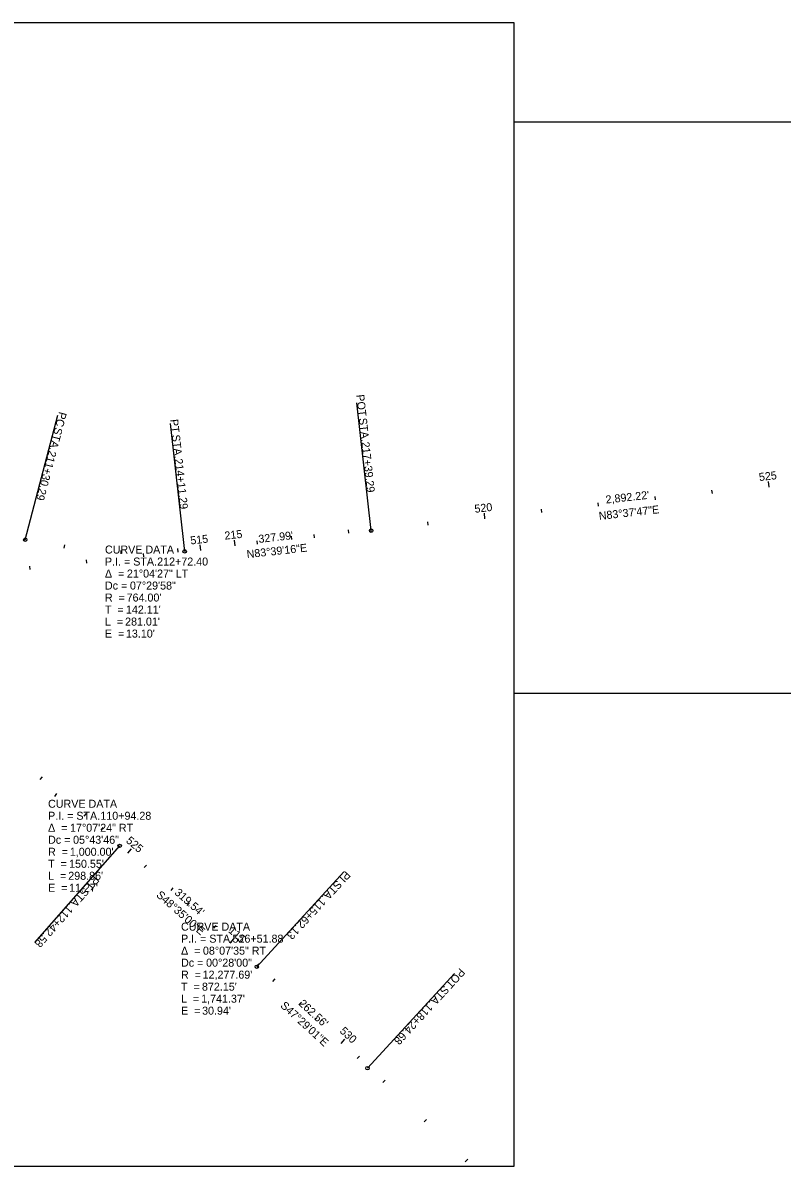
# Model space of a CAD drawing. Extents: x 1597353 to 1604853, y 283653 to 289007.
# Drawn here: x 1601495 to 1602822, y 285653 to 287653 of the extents above; entities that cross this region are included whole.
import ezdxf

# ---------------------------------------------------------------- set-up
doc = ezdxf.new("R2010")
doc.units = 0
for name, color, linetype in [('_CIVIL_CONSTRUCTION', 7, 'Continuous'), ('GE_X_Alignment_100_Cardinal_Points', 7, 'Continuous'), ('GE_X_Alignment_100_Distances', 7, 'Continuous'), ('GE_X_Alignment_100_Stations', 7, 'Continuous'), ('SH_Border', 7, 'Continuous'), ('SH_Cut_Line', 7, 'Continuous'), ('SH_Data', 7, 'Continuous'), ('SH_Masking', 7, 'Continuous'), ('SH_Named_Boundary', 7, 'Continuous'), ('SH_Text', 7, 'Continuous')]:
    doc.layers.add(name, color=color, linetype=linetype)

msp = doc.modelspace()

# ---------------------------------------------------------------- linework, layer by layer
at = {"layer": '_CIVIL_CONSTRUCTION'}
msp.add_line((1604853.4, 286480.4), (1602353.4, 286480.4), dxfattribs=at)
msp.add_lwpolyline([(1599853.4, 287653.4), (1599853.4, 285653.4), (1600103.4, 285653.4), (1600353.4, 285653.4), (1600603.4, 285653.4), (1600853.4, 285653.4), (1601103.4, 285653.4), (1601353.4, 285653.4), (1601603.4, 285653.4), (1601853.4, 285653.4), (1602103.4, 285653.4), (1602353.4, 285653.4), (1602353.4, 287653.4), (1602103.4, 287653.4), (1601853.4, 287653.4), (1601603.4, 287653.4), (1601353.4, 287653.4), (1601103.4, 287653.4), (1600853.4, 287653.4), (1600603.4, 287653.4), (1600353.4, 287653.4), (1600103.4, 287653.4)], close=True, dxfattribs=at)
msp.add_lwpolyline([(1602353.4, 286480.4), (1602353.4, 287480.4), (1604853.4, 287480.4), (1604853.4, 286480.4)], dxfattribs=at)
at = {"layer": 'GE_X_Alignment_100_Stations'}
for p, q in [((1602799.5, 286841.1), (1602798.4, 286851)), ((1602600.7, 286818.9), (1602600.1, 286824.9)), ((1602700.1, 286830), (1602699.4, 286836)), ((1602402, 286796.7), (1602401.3, 286802.7)), ((1602501.3, 286807.8), (1602500.7, 286813.8)), ((1602203.2, 286774.5), (1602202.5, 286780.5)), ((1602302.6, 286785.6), (1602301.5, 286795.6)), ((1602103.8, 286763.4), (1602103.2, 286769.4)), ((1601805.7, 286730.2), (1601804.6, 286740.1)), ((1601905.1, 286741.3), (1601904.4, 286747.2)), ((1602004.4, 286752.3), (1602003.8, 286758.3)), ((1601706.3, 286719.1), (1601705.6, 286725)), ((1601507.5, 286696.9), (1601506.9, 286702.8)), ((1601606.9, 286708), (1601606.2, 286713.9)), ((1601525.2, 286329.9), (1601529, 286334.5)), ((1601601.9, 286265.8), (1601605.8, 286270.4)), ((1601678.1, 286201), (1601684.6, 286208.6)), ((1601753.8, 286135.6), (1601757.7, 286140.2)), ((1601828.9, 286069.6), (1601832.9, 286074.1)), ((1601903.5, 286003), (1601907.5, 286007.5)), ((1601977.5, 285935.8), (1601981.6, 285940.3)), ((1602051, 285868), (1602057.9, 285875.4)), ((1602124, 285799.6), (1602128.1, 285804)), ((1602196.4, 285730.6), (1602200.5, 285735)), ((1602268.2, 285661.1), (1602272.4, 285665.4))]:
    msp.add_line(p, q, dxfattribs=at)
at = {"layer": 'SH_Border'}
for p, q in [((1602103.6, 286765.1), (1602078.8, 286988.7)), ((1601499, 286749.2), (1601556.2, 286966.9)), ((1601777.7, 286728.8), (1601752.8, 286952.4)), ((1601664, 286213.5), (1601515.2, 286044.8)), ((1601903.6, 286002.2), (1602055.7, 286168)), ((1602097.2, 285824.7), (1602249.2, 285990.6))]:
    msp.add_line(p, q, dxfattribs=at)
for centre in [(1602103.6, 286765.1), (1601499, 286749.2), (1601777.7, 286728.8), (1601664, 286213.5), (1601903.6, 286002.2), (1602097.2, 285824.7)]:
    msp.add_circle(centre, 3, dxfattribs=at)
at = {"layer": 'SH_Text'}
for p, q in [((1602064.6, 286760.7), (1602063.9, 286766.7)), ((1601567.1, 286734.6), (1601568.1, 286740.5)), ((1601865.8, 286738.6), (1601864.7, 286748.6)), ((1601965.2, 286749.7), (1601964.5, 286755.6)), ((1601666.5, 286724.6), (1601666.7, 286730.6)), ((1601766.4, 286727.7), (1601765.8, 286733.6)), ((1601550.7, 286299.9), (1601554, 286305)), ((1601631.5, 286241), (1601635.3, 286245.7)), ((1601707.1, 286175.6), (1601711, 286180.1)), ((1601782.1, 286109.4), (1601786, 286113.9)), ((1601857.1, 286043.3), (1601863.7, 286050.8)), ((1601931.6, 285976.6), (1601935.6, 285981)), ((1602005.3, 285909), (1602009.3, 285913.4)), ((1602079, 285841.4), (1602083, 285845.8))]:
    msp.add_line(p, q, dxfattribs=at)

# ---------------------------------------------------------------- texts
at = {"layer": 'GE_X_Alignment_100_Cardinal_Points'}
msp.add_text('N83°37\'47"E', height=14, rotation=6.3702, dxfattribs=at).set_placement((1602502.3, 286783.8))
at = {"layer": 'GE_X_Alignment_100_Distances'}
msp.add_text("2,892.22'", height=14, rotation=6.3702, dxfattribs=at).set_placement((1602514.3, 286812.4))
at = {"layer": 'GE_X_Alignment_100_Stations'}
for s, rotation, p in [('525', 6.3702, (1602782.2, 286851.8)), ('520', 6.3702, (1602285, 286796.2)), ('515', 6.3702, (1601788.3, 286740.8)), ('525', 319.4081, (1601674, 286220.9)), ('530', 317.0747, (1602047.6, 285888.3))]:
    msp.add_text(s, height=14, rotation=rotation, dxfattribs=at).set_placement(p)
at = {"layer": 'SH_Border'}
for s, rotation, p in [('POT', 276.3456, (1602077.4, 287002.5)), ('PC', 255.2715, (1601558.2, 286973.9)), (' STA. ', 276.3456, (1602081.4, 286966.7)), (' STA. ', 255.2715, (1601552.4, 286951.7)), ('PT', 276.3456, (1601752.2, 286959.3)), (' STA. ', 276.3456, (1601754.7, 286937.4)), ('211+30.29', 255.2715, (1601540.4, 286906)), ('217+39.29', 276.3456, (1602086.6, 286919.7)), ('214+11.29', 276.3456, (1601759.9, 286890.4)), ('PT', 228.5834, (1601619.2, 286162.4)), ('PI', 227.4836, (1602058.6, 286170.9)), (' STA. ', 228.5834, (1601604.6, 286145.8)), (' STA. ', 227.4836, (1602047.2, 286158.4)), ('115+62.13', 227.4836, (1602015.2, 286123.5)), ('112+42.58', 228.5834, (1601573.3, 286110.4)), ('POT', 227.4836, (1602258.8, 286000.7)), (' STA. ', 227.4836, (1602234.5, 285974.2)), ('118+24.68', 227.4836, (1602202.5, 285939.3))]:
    msp.add_text(s, height=14, rotation=rotation, dxfattribs=at).set_placement(p)
at = {"layer": 'SH_Cut_Line'}
for s, rotation, p in [('N83°39\'16"E', 6.3456, (1601886.8, 286716.8)), ('S48°35\'00"E', 318.5834, (1601726.9, 286126)), ('S47°29\'01"E', 317.4836, (1601943.9, 285932.7))]:
    msp.add_text(s, height=14, rotation=rotation, dxfattribs=at).set_placement(p)
at = {"layer": 'SH_Data'}
for s, p in [('CURVE DATA', (1601638.3, 286725)), ('P.I. = STA. ', (1601638.3, 286704)), ('212+72.40', (1601729.6, 286704)), ('Δ  = ', (1601638.3, 286683)), ('21°04\'27" LT', (1601676.7, 286683)), ('Dc = ', (1601638.3, 286662)), ('07°29\'58"', (1601682, 286662)), ('R  = ', (1601638.3, 286641)), ("764.00'", (1601676.2, 286641)), ('T  = ', (1601638.3, 286620)), ("142.11'", (1601675, 286620)), ('L  = ', (1601638.3, 286599)), ("281.01'", (1601673.5, 286599)), ('E  = ', (1601638.3, 286578)), ("13.10'", (1601675, 286578)), ('CURVE DATA', (1601538.9, 286280.3)), ('P.I. = STA. ', (1601538.9, 286259.3)), ('110+94.28', (1601630.3, 286259.3)), ('Δ  = ', (1601538.9, 286238.3)), ('17°07\'24" RT', (1601577.3, 286238.3)), ('Dc = ', (1601538.9, 286217.3)), ('05°43\'46"', (1601582.6, 286217.3)), ('R  = ', (1601538.9, 286196.3)), ("1,000.00'", (1601576.9, 286196.3)), ('T  = ', (1601538.9, 286175.3)), ("150.55'", (1601575.6, 286175.3)), ('L  = ', (1601538.9, 286154.3)), ("298.86'", (1601574.2, 286154.3)), ('E  = ', (1601538.9, 286133.3)), ("11.27'", (1601575.6, 286133.3))]:
    msp.add_text(s, height=14, dxfattribs=at).set_placement(p)
at = {"layer": 'SH_Masking'}
for s, rotation, p in [("327.99'", 6.3456, (1601907.4, 286743.5)), ("319.54'", 318.5834, (1601758.9, 286130.1)), ("262.56'", 317.4836, (1601975.9, 285936.2))]:
    msp.add_text(s, height=14, rotation=rotation, dxfattribs=at).set_placement(p)
at = {"layer": 'SH_Named_Boundary'}
for s, p in [('CURVE DATA', (1601771.3, 286065.3)), ('P.I. = STA. ', (1601771.3, 286044.3)), ('526+51.88', (1601861.3, 286044.3)), ('Δ  = ', (1601771.3, 286023.3)), ('08°07\'35" RT', (1601809.6, 286023.3)), ('Dc = ', (1601771.3, 286002.3)), ('00°28\'00"', (1601815.1, 286002.3)), ('R  = ', (1601771.3, 285981.3)), ("12,277.69'", (1601809, 285981.3)), ('T  = ', (1601771.3, 285960.3)), ("872.15'", (1601807.9, 285960.3)), ('L  = ', (1601771.3, 285939.3)), ("1,741.37'", (1601806.5, 285939.3)), ('E  = ', (1601771.3, 285918.3)), ("30.94'", (1601808.1, 285918.3))]:
    msp.add_text(s, height=14, dxfattribs=at).set_placement(p)
at = {"layer": 'SH_Text'}
for s, rotation, p in [('215', 6.3456, (1601848, 286749.2)), ('115', 318.5834, (1601852.9, 286063.6))]:
    msp.add_text(s, height=14, rotation=rotation, dxfattribs=at).set_placement(p)

doc.saveas('drawing.dxf')
